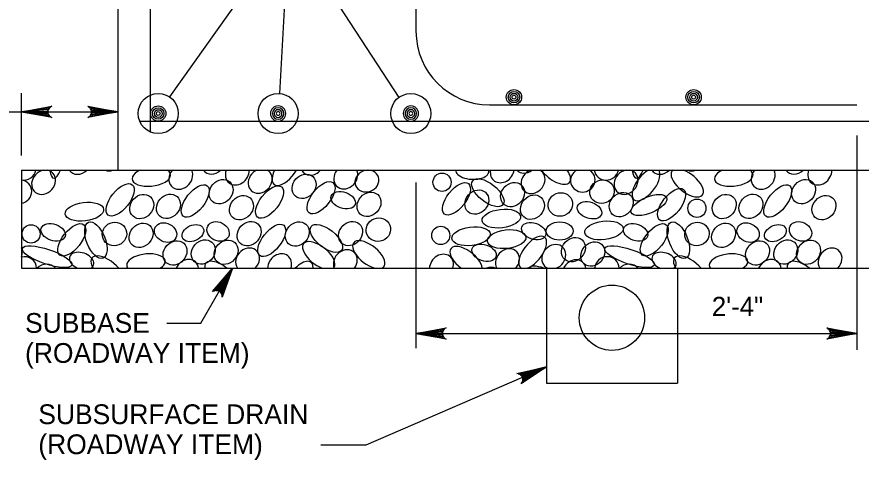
# Model space of a CAD drawing. Extents: x 638167 to 640248, y 296544 to 298920.
# Drawn here: x 638272.3 to 638403.6, y 298041.4 to 298110.3 of the extents above; entities that cross this region are included whole.
import ezdxf

# ---------------------------------------------------------------- set-up
doc = ezdxf.new("R2010")
doc.units = 0
doc.layers.add('1', color=7, linetype='Continuous')
doc.layers.add('50', color=7, linetype='Continuous')

# ---------------------------------------------------------------- blocks, each defined once
blk = doc.blocks.new('BAR')
at = {"layer": '50'}
for radius in [2, 1.5, 1, 0.5]:
    blk.add_circle((0, 0), radius, dxfattribs=at)

msp = doc.modelspace()

# ---------------------------------------------------------------- linework, layer by layer
at = {"layer": '1'}
for p, q in [((638293.1, 298092.47), (638293.1, 298182.2)), ((638334.38, 298155.65), (638334.38, 298108.03)), ((638288.02, 298154.39), (638288.02, 298086.44)), ((638314.6, 298123.94), (638296.03, 298097.85)), ((638314.6, 298123.94), (638313.14, 298098.37)), ((638314.6, 298123.94), (638331.7, 298097.74)), ((638273.02, 298088.7), (638273.02, 298098.4)), ((638345.81, 298096.6), (638402.96, 298096.6)), ((638245.2, 298095.49), (638288.02, 298095.49)), ((638291.5, 298094.06), (638578.22, 298094.06)), ((638402.96, 298091.82), (638402.96, 298058.51)), ((638273.02, 298086.44), (638273.02, 298071.2)), ((638273.02, 298086.44), (638288.02, 298086.44)), ((638288.02, 298086.44), (638583.3, 298086.44)), ((638334.38, 298084.53), (638334.38, 298058.75)), ((638273.02, 298071.2), (638598.3, 298071.2)), ((638300.94, 298062.68), (638305.83, 298071.2)), ((638354.7, 298071.2), (638354.7, 298053.33)), ((638375.03, 298071.2), (638375.03, 298053.33)), ((638295.65, 298062.68), (638300.94, 298062.68)), ((638334.38, 298061.05), (638402.96, 298061.05)), ((638326.61, 298043.77), (638354.7, 298055.88)), ((638354.7, 298053.33), (638375.03, 298053.33)), ((638319.56, 298043.77), (638326.61, 298043.77))]:
    msp.add_line(p, q, dxfattribs=at)
for points in [[(638273.02, 298095.49), (638277.72, 298096.37), (638277.54, 298096.24), (638277.36, 298096.12), (638277.26, 298095.96), (638277.17, 298095.8), (638277.14, 298095.64), (638277.12, 298095.49), (638277.14, 298095.33), (638277.17, 298095.17), (638277.26, 298095.01), (638277.36, 298094.86), (638277.54, 298094.73), (638277.72, 298094.61), (638273.02, 298095.49), (638277.54, 298094.73), (638277.36, 298094.86), (638273.02, 298095.49), (638277.26, 298095.01), (638277.17, 298095.17), (638273.02, 298095.49), (638277.14, 298095.33), (638277.12, 298095.49), (638273.02, 298095.49), (638277.14, 298095.64), (638277.17, 298095.8), (638273.02, 298095.49), (638277.26, 298095.96), (638277.36, 298096.12), (638273.02, 298095.49), (638277.54, 298096.24)], [(638288.02, 298095.49), (638283.32, 298094.61), (638283.51, 298094.73), (638283.69, 298094.86), (638283.78, 298095.01), (638283.87, 298095.17), (638283.9, 298095.33), (638283.93, 298095.49), (638283.9, 298095.64), (638283.87, 298095.8), (638283.78, 298095.96), (638283.69, 298096.12), (638283.51, 298096.24), (638283.32, 298096.37), (638288.02, 298095.49), (638283.51, 298096.24), (638283.69, 298096.12), (638288.02, 298095.49), (638283.78, 298095.96), (638283.87, 298095.8), (638288.02, 298095.49), (638283.9, 298095.64), (638283.93, 298095.49), (638288.02, 298095.49), (638283.9, 298095.33), (638283.87, 298095.17), (638288.02, 298095.49), (638283.78, 298095.01), (638283.69, 298094.86), (638288.02, 298095.49), (638283.51, 298094.73)], [(638305.83, 298071.2), (638304.26, 298066.69), (638304.24, 298066.91), (638304.22, 298067.13), (638304.13, 298067.29), (638304.04, 298067.45), (638303.92, 298067.55), (638303.79, 298067.65), (638303.64, 298067.71), (638303.49, 298067.76), (638303.31, 298067.76), (638303.13, 298067.76), (638302.93, 298067.66), (638302.73, 298067.57), (638305.83, 298071.2), (638302.93, 298067.66), (638303.13, 298067.76), (638305.83, 298071.2), (638303.31, 298067.76), (638303.49, 298067.76), (638305.83, 298071.2), (638303.64, 298067.71), (638303.79, 298067.65), (638305.83, 298071.2), (638303.92, 298067.55), (638304.04, 298067.45), (638305.83, 298071.2), (638304.13, 298067.29), (638304.22, 298067.13), (638305.83, 298071.2), (638304.24, 298066.91)], [(638334.38, 298061.05), (638339.07, 298061.93), (638338.89, 298061.81), (638338.71, 298061.68), (638338.62, 298061.52), (638338.53, 298061.37), (638338.5, 298061.21), (638338.47, 298061.05), (638338.5, 298060.89), (638338.53, 298060.74), (638338.62, 298060.58), (638338.71, 298060.42), (638338.89, 298060.3), (638339.07, 298060.17), (638334.38, 298061.05), (638338.89, 298060.3), (638338.71, 298060.42), (638334.38, 298061.05), (638338.62, 298060.58), (638338.53, 298060.74), (638334.38, 298061.05), (638338.5, 298060.89), (638338.47, 298061.05), (638334.38, 298061.05), (638338.5, 298061.21), (638338.53, 298061.37), (638334.38, 298061.05), (638338.62, 298061.52), (638338.71, 298061.68), (638334.38, 298061.05), (638338.89, 298061.81)], [(638402.96, 298061.05), (638398.26, 298060.17), (638398.44, 298060.3), (638398.62, 298060.42), (638398.71, 298060.58), (638398.81, 298060.74), (638398.83, 298060.89), (638398.86, 298061.05), (638398.83, 298061.21), (638398.81, 298061.37), (638398.71, 298061.52), (638398.62, 298061.68), (638398.44, 298061.81), (638398.26, 298061.93), (638402.96, 298061.05), (638398.44, 298061.81), (638398.62, 298061.68), (638402.96, 298061.05), (638398.71, 298061.52), (638398.81, 298061.37), (638402.96, 298061.05), (638398.83, 298061.21), (638398.86, 298061.05), (638402.96, 298061.05), (638398.83, 298060.89), (638398.81, 298060.74), (638402.96, 298061.05), (638398.71, 298060.58), (638398.62, 298060.42), (638402.96, 298061.05), (638398.44, 298060.3)], [(638354.7, 298055.88), (638350.74, 298053.21), (638350.85, 298053.39), (638350.97, 298053.58), (638350.99, 298053.76), (638351.02, 298053.94), (638350.98, 298054.1), (638350.94, 298054.25), (638350.85, 298054.39), (638350.77, 298054.52), (638350.62, 298054.63), (638350.47, 298054.74), (638350.25, 298054.78), (638350.04, 298054.82), (638354.7, 298055.88), (638350.25, 298054.78), (638350.47, 298054.74), (638354.7, 298055.88), (638350.62, 298054.63), (638350.77, 298054.52), (638354.7, 298055.88), (638350.85, 298054.39), (638350.94, 298054.25), (638354.7, 298055.88), (638350.98, 298054.1), (638351.02, 298053.94), (638354.7, 298055.88), (638350.99, 298053.76), (638350.97, 298053.58), (638354.7, 298055.88), (638350.85, 298053.39)]]:
    msp.add_lwpolyline(points, dxfattribs=at)
for centre, radius in [((638294.29, 298095.25), 3.12), ((638312.94, 298095.25), 3.12), ((638333.58, 298095.25), 3.12), ((638364.86, 298063.5), 5.08)]:
    msp.add_circle(centre, radius, dxfattribs=at)
msp.add_arc((638345.81, 298108.03), 11.43, 180, 270, dxfattribs=at)
for centre, major_axis, ratio, start_param, end_param in [((638273.4, 298086.73), (-1.78, -0.71), 0.948581, 1.006363, 2.585704), ((638276.46, 298084.57), (1.35, 1.52), 0.844245, 0.812597, 6.758242), ((638278.64, 298089.19), (0.61, 4.01), 0.282192, 2.36721, 4.002176), ((638282.03, 298087.7), (1.35, 1.52), 0.844245, 2.937326, 4.633513), ((638286.94, 298088.24), (1.35, 1.52), 0.844245, 3.456732, 4.114107), ((638293.21, 298085.41), (-2.99, -0.36), 0.479042, 5.260141, 9.956857), ((638292.59, 298088.95), (-1.86, -2.36), 0.479042, 0.238343, 0.481611), ((638295.84, 298088.32), (1.35, 1.52), 0.844245, 3.627473, 3.943366), ((638297.79, 298085.38), (1.35, 1.52), 0.844245, 1.619643, 5.951196), ((638302.87, 298087.74), (1.35, 1.52), 0.844245, 2.967408, 4.603431), ((638306.59, 298086.05), (1.35, 1.52), 0.844245, 2.008108, 5.562731), ((638310.15, 298084.75), (1.35, 1.52), 0.844245, 1.11244, 6.458399), ((638314.17, 298086.59), (-1.86, -2.36), 0.479042, 5.130486, 8.155839), ((638318.24, 298087.56), (1.35, 1.52), 0.844245, 2.840874, 4.729965), ((638323.46, 298085.42), (1.35, 1.52), 0.844245, 1.646659, 5.92418), ((638326.75, 298084.75), (-1.76, -0.7), 0.87402, 4.347672, 10.501851), ((638343.14, 298086.32), (2.57, -0.11), 0.504072, 3.123827, 6.463685), ((638347.8, 298086.39), (1.35, 1.52), 0.844245, 2.187172, 5.383667), ((638351.48, 298087.89), (1.35, 1.52), 0.844245, 3.07937, 4.491469), ((638352.59, 298084.71), (1.35, 1.52), 0.844245, 1.061779, 6.50906), ((638355.91, 298086.42), (-2.36, 1.86), 0.479042, 1.014341, 4.173787), ((638360.33, 298084.88), (-1.78, -0.71), 0.948581, 4.858014, 10.05193), ((638364, 298086.73), (-1.78, -0.71), 0.948581, 6.041055, 8.868889), ((638367.05, 298084.57), (1.35, 1.52), 0.844245, 0.812597, 6.758242), ((638370.15, 298084.21), (-1.86, -2.36), 0.479042, 3.984367, 9.301958), ((638369.24, 298089.19), (0.61, 4.01), 0.282192, 2.36721, 4.002176), ((638372.63, 298087.7), (1.35, 1.52), 0.844245, 2.937326, 4.633513), ((638376.57, 298084.45), (-2.36, 1.86), 0.479042, 6.144575, 11.609923), ((638377.54, 298088.24), (1.35, 1.52), 0.844245, 3.456732, 4.114107), ((638383.8, 298085.41), (-2.99, -0.36), 0.479042, 5.260141, 9.956857), ((638383.18, 298088.95), (-1.86, -2.36), 0.479042, 0.238343, 0.481611), ((638386.43, 298088.32), (1.35, 1.52), 0.844245, 3.627473, 3.943366), ((638388.38, 298085.38), (1.35, 1.52), 0.844245, 1.619643, 5.951196), ((638393.47, 298087.74), (1.35, 1.52), 0.844245, 2.967408, 4.603431), ((638397.18, 298086.05), (1.35, 1.52), 0.844245, 2.008108, 5.562731), ((638272.71, 298083.09), (-1.78, -0.71), 0.948581, 1.372097, 4.185875), ((638352.52, 298073.65), (-1.86, -2.36), 0.479042, 0.613344, 6.389796), ((638271.28, 298073.41), (1.35, 1.52), 0.844245, 5.154902, 5.892272), ((638308.19, 298072.44), (1.35, 1.52), 0.844245, 4.644979, 9.209045), ((638319.26, 298073.17), (-2.36, 1.86), 0.479042, 3.037298, 8.434015), ((638323.39, 298072.18), (1.35, 1.52), 0.844245, 4.815265, 9.038759), ((638327.04, 298073.3), (-2.36, 1.86), 0.479042, 2.873239, 8.598074), ((638342.18, 298072.42), (-2.36, 1.86), 0.479042, 3.57213, 7.899183), ((638348.61, 298072.33), (1.35, 1.52), 0.844245, 4.720434, 9.133591), ((638355.81, 298072.98), (1.35, 1.52), 0.844245, 4.147339, 9.706685), ((638398.78, 298072.44), (1.35, 1.52), 0.844245, 4.644979, 9.209045), ((638273.46, 298071.16), (-1.78, -0.71), 0.948581, 2.768835, 4.584774), ((638282.37, 298072.32), (1.85, -0.65), 0.646802, 5.825434, 10.881517), ((638286.35, 298070.94), (-2.36, 1.86), 0.479042, 4.285286, 7.186027), ((638292.38, 298071.97), (-2.99, -0.36), 0.479042, 2.351329, 6.582484), ((638313.17, 298071.54), (1.35, 1.52), 0.844245, 5.179508, 8.674516), ((638338.34, 298071.48), (1.35, 1.52), 0.844245, 5.210279, 8.643745), ((638364.06, 298071.16), (-1.78, -0.71), 0.948581, 2.768835, 5.857924), ((638372.97, 298072.32), (1.85, -0.65), 0.646802, 5.825434, 10.881517), ((638376.94, 298070.94), (-2.36, 1.86), 0.479042, 4.285286, 7.186027), ((638382.98, 298071.97), (-2.99, -0.36), 0.479042, 2.351329, 6.582484), ((638276.85, 298069.99), (-1.78, -0.71), 0.948581, 3.464469, 5.16229), ((638298.73, 298070.66), (1.35, 1.52), 0.844245, 5.644884, 8.209141), ((638304.03, 298070.11), (-2.36, 1.86), 0.479042, 4.69169, 6.779622), ((638316.22, 298069.76), (-1.86, -2.36), 0.479042, 2.538262, 4.464878), ((638355.67, 298069.33), (3.55, -1.95), 0.282192, 2.12602, 3.204967), ((638358.97, 298070.61), (1.35, 1.52), 0.844245, 5.676034, 8.17799), ((638367.44, 298069.99), (-1.78, -0.71), 0.948581, 3.464469, 5.16229), ((638389.33, 298070.66), (1.35, 1.52), 0.844245, 5.644884, 8.209141), ((638394.63, 298070.11), (-2.36, 1.86), 0.479042, 4.69169, 6.779622), ((638345.77, 298069.45), (1.35, 1.52), 0.844245, 0.243434, 1.04422)]:
    msp.add_ellipse(centre, major_axis=major_axis, ratio=ratio, start_param=start_param, end_param=end_param, dxfattribs=at)
for centre, major_axis, ratio in [((638316.97, 298083.94), (1.35, 1.52), 0.844245), ((638304.07, 298083.1), (1.35, 1.52), 0.844245), ((638319.61, 298082.16), (-1.86, -2.36), 0.479042), ((638338.43, 298084.56), (0, 1.43), 0.982495), ((638340.67, 298081.99), (-1.86, -2.36), 0.479042), ((638345.56, 298082.94), (-2.36, 1.86), 0.479042), ((638349.4, 298082.65), (1.35, 1.52), 0.844245), ((638363.31, 298083.09), (-1.78, -0.71), 0.948581), ((638394.67, 298083.1), (1.35, 1.52), 0.844245), ((638288.37, 298081.83), (-1.86, -2.36), 0.479042), ((638300.05, 298081.65), (-1.86, -2.36), 0.479042), ((638311.6, 298081.48), (-1.86, -2.36), 0.479042), ((638343.84, 298081.48), (1.35, 1.52), 0.844245), ((638374.13, 298081.08), (-1.86, -2.36), 0.479042), ((638390.64, 298081.65), (-1.86, -2.36), 0.479042), ((638291.72, 298080.79), (1.35, 1.52), 0.844245), ((638295.87, 298080.81), (1.35, 1.52), 0.844245), ((638307.23, 298080.6), (1.35, 1.52), 0.844245), ((638323.05, 298081.77), (1.85, -0.65), 0.646802), ((638327.07, 298081.12), (1.35, 1.52), 0.844245), ((638352.49, 298080.69), (1.35, 1.52), 0.844245), ((638356.83, 298081.11), (-1.78, -0.71), 0.948581), ((638366.3, 298081.09), (1.35, 1.52), 0.844245), ((638370.61, 298081.03), (2.75, 1.17), 0.422273), ((638382.32, 298080.79), (1.35, 1.52), 0.844245), ((638386.47, 298080.81), (1.35, 1.52), 0.844245), ((638397.83, 298080.6), (1.35, 1.52), 0.844245), ((638282.81, 298079.99), (-2.99, -0.36), 0.479042), ((638361.37, 298080.21), (1.85, -0.65), 0.646802), ((638378.08, 298080.53), (0, 1.43), 0.982495), ((638347.65, 298078.92), (-2.99, -0.36), 0.479042), ((638277.95, 298076.78), (1.85, -0.65), 0.646802), ((638280.84, 298075.61), (-1.86, -2.36), 0.479042), ((638284.59, 298075.56), (1.12, -2.79), 0.479042), ((638287.49, 298076.52), (-1.78, -0.71), 0.948581), ((638291.62, 298076.31), (1.35, 1.52), 0.844245), ((638295.44, 298076.74), (1.61, -0.83), 0.796199), ((638299.68, 298076.66), (1.62, 0.73), 0.687276), ((638303.59, 298076.92), (1.61, -0.83), 0.796199), ((638308.43, 298076.58), (1.35, 1.52), 0.844245), ((638311.94, 298075.52), (-1.86, -2.36), 0.479042), ((638315.91, 298076.51), (1.35, 1.52), 0.844245), ((638320.44, 298075.83), (-2.36, 1.86), 0.479042), ((638324.2, 298076.59), (1.35, 1.52), 0.844245), ((638328.53, 298077.19), (-1.78, -0.71), 0.948581), ((638352.69, 298076.96), (1.85, -0.65), 0.646802), ((638356.72, 298076.98), (2.11, 0), 0.671766), ((638363.62, 298077.08), (-2.99, -0.36), 0.479042), ((638368.54, 298076.78), (1.85, -0.65), 0.646802), ((638371.44, 298075.61), (-1.86, -2.36), 0.479042), ((638375.19, 298075.56), (1.12, -2.79), 0.479042), ((638378.08, 298076.52), (-1.78, -0.71), 0.948581), ((638382.22, 298076.31), (1.35, 1.52), 0.844245), ((638386.03, 298076.74), (1.61, -0.83), 0.796199), ((638390.28, 298076.66), (1.62, 0.73), 0.687276), ((638394.19, 298076.92), (1.61, -0.83), 0.796199), ((638274.51, 298076.53), (0, 1.43), 0.982495), ((638338.23, 298076.3), (0, 1.43), 0.982495), ((638342.95, 298076.17), (-2.99, -0.36), 0.479042), ((638348.48, 298075.72), (-2.99, -0.36), 0.479042), ((638296.9, 298073.58), (1.35, 1.52), 0.844245), ((638301.29, 298073.71), (1.35, 1.52), 0.844245), ((638304.84, 298073.69), (1.35, 1.52), 0.844245), ((638358.86, 298074.1), (1.35, 1.52), 0.844245), ((638361.88, 298073.41), (1.35, 1.52), 0.844245), ((638387.5, 298073.58), (1.35, 1.52), 0.844245), ((638391.89, 298073.71), (1.35, 1.52), 0.844245), ((638395.43, 298073.69), (1.35, 1.52), 0.844245), ((638277, 298072.99), (3.84, -1.3), 0.282192), ((638344.97, 298073.6), (1.85, -0.65), 0.646802), ((638367.6, 298072.99), (3.84, -1.3), 0.282192)]:
    msp.add_ellipse(centre, major_axis=major_axis, ratio=ratio, dxfattribs=at)

# ---------------------------------------------------------------- block references
at = {"layer": '1', "xscale": 0.5953136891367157}
for p, yscale, rotation in [((638349.62, 298097.79), 0.5953136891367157, -90.00000000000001), ((638377.56, 298097.79), 0.5953136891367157, -90.00000000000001), ((638294.29, 298095.25), 0.5953136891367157, -90.00000000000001), ((638312.94, 298095.25), -0.5953136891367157, -89.99999999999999), ((638333.58, 298095.25), -0.5953136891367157, -89.99999999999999)]:
    msp.add_blockref('BAR', p, dxfattribs=dict(at, yscale=yscale, rotation=rotation))

# ---------------------------------------------------------------- texts
at = {"layer": '1'}
for s, height, p in [('2\'-4"', 3, (638380.39, 298063.76)), ('SUBBASE', 3.072, (638273.58, 298061.16)), ('(ROADWAY ITEM)', 3.072, (638273.58, 298056.49))]:
    msp.add_text(s, height=height, dxfattribs=at).set_placement(p)
for s, p in [('SUBSURFACE DRAIN', (638275.64, 298046.97)), ('(ROADWAY ITEM)', (638275.64, 298042.3))]:
    msp.add_text(s, height=3.072, rotation=360, dxfattribs=at).set_placement(p)

doc.saveas('drawing.dxf')
